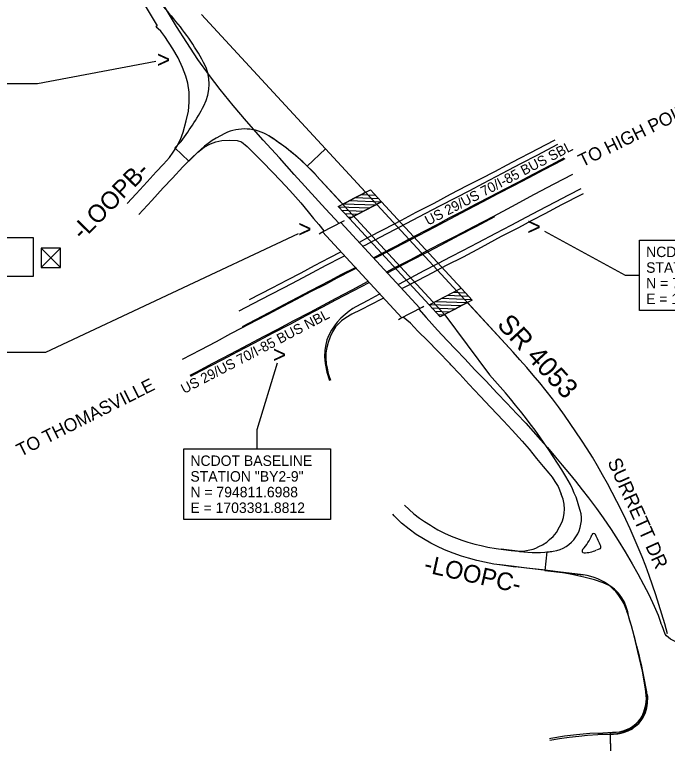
# Model space of a CAD drawing. Extents: x 1701144 to 1707001, y 793349 to 797175.
# Drawn here: x 1702973 to 1703974, y 794216 to 795332 of the extents above; entities that cross this region are included whole.
import ezdxf

# ---------------------------------------------------------------- set-up
doc = ezdxf.new("R2010")
doc.units = 0
for name, color, linetype in [('CTL Sheet Text', 7, 'Continuous'), ('Default', 7, 'Continuous'), ('Exist Property Titlesheet Border PSD CELL', 7, 'Continuous'), ('Old_Level_3', 7, 'Continuous'), ('Old_Level_4', 7, 'Continuous'), ('Old_Level_57', 7, 'Continuous'), ('Prop Approach Slab', 7, 'Continuous'), ('Prop EOT', 7, 'Continuous'), ('Prop Roadway Bridge', 7, 'Continuous'), ('Proposed Right of Way Monument PSD Leader', 7, 'Continuous'), ('Proposed Right of Way Monument PSD Text', 7, 'Continuous'), ('Sheet Title CELL', 7, 'Continuous')]:
    doc.layers.add(name, color=color, linetype=linetype)

msp = doc.modelspace()

# ---------------------------------------------------------------- linework, layer by layer
at = {"layer": 'Default'}
for p, q in [((1703449.8, 795126.4), (1703259.9, 795332.1)), ((1703225.7, 795134.5), (1703218.7, 795127.9)), ((1703218.7, 795127.9), (1703240.5, 795107.5)), ((1703421.5, 795100.2), (1703449.8, 795126.4)), ((1703449.8, 795126.4), (1703421.5, 795100.2)), ((1703511, 795060.1), (1703449.8, 795126.4)), ((1703240.5, 795107.5), (1703248.1, 795115.5)), ((1703435.6, 795085.8), (1703476.2, 795041.8)), ((1703504.1, 795056.5), (1703511, 795060.1)), ((1703476.2, 795041.8), (1703477.5, 795042.5)), ((1703477.5, 795042.5), (1703486.4, 795047.2)), ((1703658.2, 794886.5), (1703649.3, 794881.8)), ((1703667, 794891.1), (1703658.2, 794886.5)), ((1703658.2, 794886.5), (1703658.2, 794886.5)), ((1703658.2, 794886.5), (1703658.2, 794886.5)), ((1703640.4, 794877.2), (1703632.1, 794872.9)), ((1703632.1, 794872.9), (1703632.4, 794872.5)), ((1703632.4, 794872.5), (1703701.1, 794780.4)), ((1703649.3, 794881.8), (1703640.4, 794877.2)), ((1703640.4, 794877.2), (1703640.4, 794877.2)), ((1703640.4, 794877.2), (1703640.4, 794877.2)), ((1703649.3, 794881.8), (1703649.3, 794881.8)), ((1703649.3, 794881.8), (1703649.3, 794881.8)), ((1703788.9, 794509.3), (1703785.5, 794481.1)), ((1703785.5, 794481.1), (1703844.6, 794474)), ((1703890.3, 794230.5), (1703885.6, 794230.3)), ((1703885.6, 794230.3), (1703886.4, 794202.2))]:
    msp.add_line(p, q, dxfattribs=at)
for points in [[(1703486.4, 795047.2), (1703495.2, 795051.8), (1703504.1, 795056.5)], [(1703737.1, 794815.1), (1703667.1, 794891.1), (1703667, 794891.1)]]:
    msp.add_lwpolyline(points, dxfattribs=at)
msp.add_lwpolyline([(1702806, 794990.9), (1703001.6, 794990.9), (1703001.6, 794930.9), (1702806, 794930.9)], close=True, dxfattribs=at)
for centre, radius, start, end in [((1703981.5, 795998.2), 1018, 215.0107, 221.0304), ((1702911.8, 795067.4), 400, 28.6224, 41.0304), ((1703201.5, 795225.4), 70, 332.0106, 28.6224), ((1702910.1, 795380.3), 400, 322.0902, 332.0106), ((1703325.6, 795087), 70, 57.7993, 115.717), ((1703364.7, 795005.9), 160, 115.717, 136.7565), ((1703171.1, 794841.6), 360, 45.9217, 57.7993), ((1703171.1, 794841.6), 360, 42.7091, 45.9217), ((1702989.1, 794124.6), 1018, 14.7589, 42.7091), ((1702989.1, 794124.6), 968, 31.1029, 42.644), ((1703646.7, 794521.4), 200, 14.8969, 31.1029), ((1703791.7, 794559.9), 50, 277.9887, 14.8969), ((1703770.8, 794708.5), 200, 275.1944, 277.9887), ((1703835.1, 794394.6), 80, 17.697, 83.1536), ((1702989.1, 794124.6), 968, 10.146, 17.697), ((1703887.8, 794285.5), 55, 272.5979, 10.146)]:
    msp.add_arc(centre, radius, start, end, dxfattribs=at)
at = {"layer": 'Exist Property Titlesheet Border PSD CELL'}
for points in [[(1703930.9, 794986.8), (1704155.5, 794986.8), (1704155.5, 794878.8), (1703930.9, 794878.8)], [(1703232.7, 794667), (1703457.3, 794667), (1703457.3, 794559), (1703232.7, 794559)]]:
    msp.add_lwpolyline(points, close=True, dxfattribs=at)
at = {"layer": 'Old_Level_3'}
for points in [[(1703167.6, 795356.3), (1703171.7, 795348.1), (1703180.9, 795332.8), (1703191.9, 795315), (1703189.8, 795313.5)], [(1703418.2, 795069.3), (1703401.7, 795087.5), (1703379, 795112.6), (1703354.2, 795139.9), (1703328.7, 795168.8), (1703308, 795193), (1703288.1, 795217.4), (1703271.7, 795238.9), (1703254.2, 795263.5), (1703237.1, 795289.4), (1703221.3, 795314.1), (1703203, 795344.6)], [(1703145.6, 795042.7), (1703159.4, 795057.7), (1703176.4, 795076.1), (1703190.4, 795091.1), (1703201.5, 795103.1), (1703210.6, 795113.4), (1703216.4, 795121.4), (1703222, 795130.2), (1703227.5, 795140.7), (1703231.4, 795152.1), (1703236.1, 795169.3), (1703239.6, 795184.4), (1703240.7, 795197.8), (1703240.8, 795213.5), (1703238.9, 795226.9), (1703235.9, 795237.7), (1703230.6, 795251.2), (1703223.9, 795265.8), (1703215.6, 795279.8), (1703203.6, 795298.5), (1703197.6, 795306.6), (1703193.5, 795310.3), (1703190.1, 795313)], [(1703641.3, 795056.9), (1703666.7, 795070.3), (1703688.3, 795081.2), (1703708.9, 795091.9), (1703727.9, 795102), (1703746.4, 795111.8), (1703764.4, 795120.9), (1703786.8, 795132.8), (1703801.5, 795140.3)], [(1703163.8, 795025.9), (1703183.4, 795047.6), (1703201, 795066.7), (1703215, 795081.9), (1703231.1, 795099.2), (1703243.7, 795111.8), (1703254, 795121.4), (1703264, 795128.9), (1703273.7, 795134.1), (1703281.8, 795137.4), (1703290.8, 795139.5), (1703302.6, 795139.6), (1703314.3, 795139.5), (1703320.8, 795137.4), (1703329.8, 795130.2), (1703351.4, 795108.4), (1703369.9, 795089.4), (1703388.8, 795069.2), (1703399.7, 795057.6)], [(1703804.9, 795133), (1703796.3, 795128.6), (1703774.5, 795117.1), (1703748.6, 795103.5), (1703720.1, 795088.7), (1703691.4, 795073.7), (1703670.1, 795062.4), (1703649.1, 795051.6), (1703624.3, 795038.9)], [(1703816.3, 795111), (1703812.6, 795109.1), (1703784.4, 795094.5), (1703761.4, 795082.3), (1703736.8, 795069.6), (1703713.8, 795057.6), (1703690.6, 795045.5), (1703666.3, 795032.6), (1703639.9, 795018.9)], [(1703657.6, 795030.1), (1703681.7, 795042.7), (1703702.3, 795053.4), (1703723.9, 795064.8), (1703744.8, 795075.7), (1703768.9, 795088.3), (1703795.5, 795102.3), (1703815.3, 795112.6)], [(1703553.8, 794943.6), (1703580.2, 794957.3), (1703601.6, 794968.7), (1703625.3, 794980.9), (1703649.6, 794993.3), (1703676.8, 795007.7), (1703707.5, 795023.6), (1703735.3, 795038.4), (1703770, 795057), (1703800.1, 795072.9), (1703828.4, 795087.7)], [(1703418.2, 795069.3), (1703438.9, 795046.4), (1703449.8, 795034.7), (1703464.1, 795019.5), (1703470.3, 795012.7)], [(1703840.6, 795065.3), (1703821.9, 795055.4), (1703801.4, 795044.9), (1703775.9, 795031.5), (1703757.6, 795021.8), (1703733.6, 795009.3), (1703710.1, 794996.8), (1703682.9, 794982.6)], [(1703399.7, 795057.6), (1703412, 795043.8), (1703423, 795030.3), (1703431.4, 795020), (1703439.3, 795010.5), (1703447.2, 795001)], [(1703501.5, 794983.8), (1703514.6, 794990.7), (1703539.7, 795003.6), (1703566, 795017.5), (1703588.8, 795029.4), (1703616.1, 795043.6), (1703641.3, 795056.9)], [(1703844.4, 795057.9), (1703842.2, 795056.7), (1703811.3, 795040.6), (1703785.7, 795027), (1703765.6, 795016.7), (1703745.2, 795005.7), (1703719, 794992.1), (1703688.3, 794975.5), (1703660.8, 794960.9), (1703634.4, 794948.1)], [(1703624.3, 795038.9), (1703603, 795027.7), (1703582.4, 795016.7), (1703556.3, 795003), (1703532.1, 794990.5), (1703509.9, 794978.7), (1703507.2, 794977.3)], [(1703523.1, 794959.7), (1703533.6, 794965.2), (1703558.3, 794978.2), (1703576.3, 794987.5), (1703601.7, 795000.9), (1703621.7, 795011.2), (1703639.2, 795020.8), (1703657.6, 795030.1)], [(1703639.9, 795018.9), (1703616.1, 795006.3), (1703592.5, 794994.1), (1703568, 794981.2), (1703547.9, 794970.6), (1703526.7, 794959.8), (1703524.1, 794958.5)], [(1703544.8, 794936.7), (1703553.5, 794941.3), (1703580.5, 794955.6), (1703606.6, 794969.1), (1703627, 794979.6), (1703654.7, 794994.2), (1703680.4, 795007.6), (1703709.1, 795022.8)], [(1703682.9, 794982.6), (1703659.8, 794970.5), (1703641.8, 794961.2), (1703621.4, 794950.4), (1703600.4, 794939.5), (1703580.4, 794929), (1703562.3, 794919.2), (1703561.5, 794918.8)], [(1703333.4, 794895.8), (1703367.7, 794913.7), (1703391.2, 794926.1), (1703412.4, 794936.9), (1703432.7, 794947.8), (1703456.1, 794960.1), (1703473.4, 794968.9)], [(1703479.1, 794962.8), (1703474.4, 794960.4)], [(1703474.4, 794960.4), (1703450.3, 794947.8), (1703429, 794936.5), (1703407.2, 794925.2), (1703385.6, 794913.9), (1703364.9, 794903.2), (1703338.5, 794889.1), (1703316.9, 794878)], [(1703497.1, 794943.8), (1703490.2, 794940.1), (1703467.2, 794928.3), (1703449.5, 794919), (1703427.5, 794907.9), (1703404.5, 794895.8), (1703383.5, 794884.8), (1703361.2, 794872.9), (1703343.6, 794863.7), (1703320.8, 794851.9), (1703304.3, 794843.3), (1703281.9, 794831.2), (1703257.8, 794818.4), (1703229.9, 794803.9)], [(1703322.4, 794854.4), (1703342.8, 794865.2), (1703363.4, 794876), (1703386.5, 794888), (1703407.9, 794899.3), (1703426.2, 794909), (1703441.8, 794917.1), (1703457, 794925.2), (1703474.8, 794934.4), (1703495.4, 794945.1)], [(1703543.4, 794938.2), (1703553.8, 794943.6)], [(1703634.4, 794948.1), (1703605, 794932.2), (1703570.1, 794914.4), (1703566.9, 794912.8)], [(1703242.3, 794780), (1703252.3, 794785.2), (1703276.8, 794798.4), (1703304.5, 794812.9), (1703331.5, 794827.1), (1703354.8, 794839.3), (1703376.6, 794850.6), (1703401.3, 794863.6), (1703426.4, 794876.6), (1703445.9, 794887), (1703466.1, 794897.8), (1703490.6, 794910.9), (1703515.2, 794923.7)], [(1703445.6, 794884.8), (1703465.5, 794895.2), (1703493.2, 794909.7), (1703516.8, 794921.9)], [(1703538.8, 794898), (1703535.5, 794896.3), (1703503.7, 794880), (1703489.9, 794873.3), (1703480.8, 794867.9), (1703474.4, 794863.1), (1703469.9, 794859.2), (1703465.2, 794853.8), (1703460.5, 794846.2), (1703456.8, 794838.5), (1703453.5, 794830.1), (1703451.5, 794822.3), (1703450.4, 794814), (1703450.1, 794806.1), (1703450.9, 794797.5), (1703452.1, 794791.3), (1703453.4, 794784.7), (1703454.9, 794779.5), (1703457.4, 794772.5)], [(1703533.3, 794904.4), (1703531.3, 794903.3), (1703514.4, 794894.4), (1703495.9, 794884.6)], [(1703243.3, 794778.4), (1703248, 794780.9), (1703274.6, 794794.9), (1703292.4, 794804.1), (1703315.2, 794816.2), (1703341, 794829.7), (1703368.4, 794844.1), (1703395.3, 794858.1), (1703419.9, 794871.1), (1703445.6, 794884.8)], [(1703495.9, 794884.6), (1703491.4, 794882.2), (1703485.9, 794878), (1703480, 794873.1), (1703473.4, 794867.1), (1703467.5, 794861.3), (1703463.2, 794855.6), (1703458.8, 794849.1), (1703454.6, 794841.2), (1703451.9, 794834.1), (1703450, 794826.7), (1703448.6, 794818.4), (1703448.3, 794807.9), (1703449, 794797.8), (1703451.8, 794784.6), (1703455.6, 794771.9)], [(1703592.7, 794881), (1703604, 794868.1), (1703621.2, 794849.1), (1703636.1, 794833.2), (1703649.1, 794819.4), (1703663.1, 794804.9), (1703678.7, 794788.1), (1703695.1, 794771.1), (1703712.9, 794752.3), (1703727.4, 794737), (1703742.7, 794720.6), (1703756.4, 794706.3), (1703767.6, 794693.8), (1703779.2, 794680.9), (1703789.6, 794669.2), (1703802, 794654.4), (1703812.3, 794642.3), (1703823.3, 794628.9), (1703832.6, 794617.6), (1703842.9, 794604.6), (1703852.7, 794591.9), (1703864.9, 794575.6), (1703875.1, 794561.5), (1703887.2, 794543.8), (1703898.1, 794526.8), (1703908.6, 794509.4), (1703919.6, 794491), (1703928.4, 794475.7), (1703937, 794459.5), (1703945, 794443.9), (1703953.2, 794426.2), (1703959.1, 794412.4), (1703963.5, 794400.4)], [(1703641.7, 794796), (1703640.5, 794797.3), (1703621.6, 794816.8), (1703606.4, 794832.6), (1703591.3, 794847.6), (1703579.8, 794859.4), (1703568.9, 794869)], [(1703641.7, 794796), (1703655.4, 794781.3), (1703669.5, 794766.4), (1703686.6, 794748), (1703702.3, 794731.2), (1703722.2, 794710.1), (1703735.4, 794695.8), (1703750.8, 794678.8), (1703761.5, 794666.8), (1703773.1, 794652.4), (1703783.3, 794640.2), (1703791.8, 794630), (1703796.8, 794623.6), (1703801.1, 794617.2), (1703805.9, 794609.5), (1703810.9, 794598)], [(1703570.9, 794580.8), (1703577.8, 794574.1), (1703584.9, 794567.9), (1703593.7, 794561), (1703601.2, 794555.9), (1703610.3, 794550.1), (1703614.9, 794547.2), (1703622, 794543.2), (1703632, 794538.1), (1703642.1, 794533.6), (1703650.3, 794530.4), (1703658.4, 794527.5), (1703667.9, 794524.3), (1703678.3, 794521.3), (1703688, 794519), (1703698.5, 794516.8), (1703710.9, 794514.4), (1703722.4, 794512.8), (1703734, 794511.3), (1703745.5, 794510.6), (1703752.4, 794510.7), (1703757.6, 794511.4), (1703762.5, 794512.3), (1703767.6, 794513.7), (1703771.9, 794515.2), (1703776.4, 794517.4), (1703782.2, 794520.3), (1703788.6, 794524.5), (1703793, 794528.2), (1703798.5, 794532.9), (1703803.4, 794538.9), (1703808.3, 794547.8), (1703812, 794555.6), (1703814.1, 794562), (1703815.5, 794568.8), (1703815.9, 794574.9), (1703815.4, 794582.3), (1703813.8, 794590.2), (1703810.9, 794598)], [(1703923.2, 794378.6), (1703918.6, 794396.1), (1703914.6, 794409.3), (1703912.8, 794417.7), (1703910.5, 794425.4), (1703907.5, 794432.5), (1703903.6, 794439), (1703898.5, 794446), (1703892.5, 794452.3), (1703885.3, 794457.6), (1703875.3, 794462.1), (1703861.6, 794466.7), (1703845.3, 794470.9), (1703827, 794474.7), (1703805.5, 794478.6), (1703782.1, 794482), (1703757.7, 794484.7), (1703738.8, 794486.8), (1703721.9, 794488.8), (1703707.8, 794490.6), (1703693.4, 794493.5), (1703681.6, 794496), (1703668.5, 794499.6), (1703657.9, 794502.8), (1703645.3, 794507.3), (1703632.2, 794512.7), (1703620.2, 794518.1), (1703611.1, 794522.7), (1703599.7, 794529.4), (1703588.7, 794536.2), (1703577.7, 794544.2), (1703566.3, 794553.6), (1703554.9, 794564.4), (1703552.6, 794566.9)], [(1704043.7, 794444.9), (1704039.7, 794420.4), (1704035.4, 794403), (1704031.7, 794391.8), (1704027.1, 794381.3), (1704020.5, 794372.2), (1704013.2, 794367.6), (1704006.7, 794365), (1703997.6, 794366.2), (1703986.4, 794371.5), (1703978, 794375.9), (1703971.9, 794380.8), (1703969.9, 794383.6), (1703965.5, 794396), (1703963.5, 794400.4)], [(1703940.7, 794289.9), (1703939.8, 794299.5), (1703935.3, 794326.7), (1703928.4, 794357), (1703923.2, 794378.6)], [(1703792.7, 794223.6), (1703795.1, 794224), (1703815.9, 794227.6), (1703834.4, 794229.8), (1703854.5, 794231.9), (1703874.6, 794232.5), (1703889.3, 794233.1), (1703895.2, 794233.2), (1703900.2, 794234), (1703905.6, 794235.2), (1703910.8, 794237.2), (1703915.7, 794239.5), (1703920.6, 794242.7), (1703924.9, 794246), (1703929, 794250.1), (1703932.1, 794253.9), (1703934.6, 794258), (1703937.5, 794264.4), (1703940.5, 794275.2), (1703941.2, 794284.2), (1703940.7, 794289.9)], [(1703793.1, 794220.9), (1703793.1, 794220.9), (1703808.4, 794223.4), (1703823, 794225.6), (1703837.6, 794227.3), (1703851.1, 794228.6), (1703866.9, 794229.6), (1703881.7, 794230.1), (1703890.8, 794230.4), (1703897.3, 794230.9), (1703902.6, 794231.9), (1703907.7, 794233.3), (1703913.6, 794235.4), (1703919.8, 794238.6), (1703924.7, 794242.3), (1703929.7, 794246.6), (1703933.4, 794251), (1703936.4, 794255.9), (1703939.9, 794263.3), (1703942, 794270.7), (1703943.1, 794277.9), (1703943.3, 794287.3), (1703942.9, 794290.8)]]:
    msp.add_lwpolyline(points, dxfattribs=at)
at = {"layer": 'Old_Level_4'}
for points in [[(1703439.9, 794996.6), (1703444.2, 794999), (1703476.5, 795015.7), (1703478.7, 795016.8)], [(1703594.4, 794882.7), (1703473.3, 795013.7)], [(1703445.1, 794999.6), (1703566.6, 794867.9)], [(1703561.4, 794865.4), (1703564.2, 794866.6), (1703597.7, 794884.2), (1703600.4, 794885.5)]]:
    msp.add_lwpolyline(points, dxfattribs=at)
at = {"layer": 'Old_Level_57'}
for p, q in [((1703013.9, 794974.6), (1703043.4, 794945.1)), ((1703043.4, 794974.6), (1703013.9, 794945.1))]:
    msp.add_line(p, q, dxfattribs=at)
msp.add_lwpolyline([(1703013.9, 794945.1), (1703043.4, 794945.1), (1703043.4, 794974.6), (1703013.9, 794974.6)], close=True, dxfattribs=at)
for points in [[(1703028.6, 794959.9), (1703043.4, 794974.6), (1703013.9, 794974.6), (1703028.6, 794959.9)], [(1703028.6, 794959.9), (1703013.9, 794945.1), (1703043.4, 794945.1), (1703028.6, 794959.9)]]:
    msp.add_lwpolyline(points, dxfattribs=at)
at = {"layer": 'Prop Approach Slab'}
for p, q in [((1703469.3, 795038.2), (1703518.4, 795064)), ((1703518.4, 795064), (1703535.3, 795045.6)), ((1703495.2, 795051.8), (1703530.8, 795050.4)), ((1703504.1, 795056.5), (1703526, 795055.6)), ((1703477.5, 795042.5), (1703525.8, 795040.6)), ((1703486.2, 795019.9), (1703530.3, 795042.9)), ((1703486.4, 795047.2), (1703534.7, 795045.3)), ((1703486.2, 795019.9), (1703469.3, 795038.2)), ((1703469.6, 795037.9), (1703517, 795036)), ((1703474.4, 795032.7), (1703508.1, 795031.3)), ((1703479.2, 795027.5), (1703499.2, 795026.7)), ((1703484, 795022.3), (1703490.3, 795022)), ((1703653.2, 794917.8), (1703674.4, 794894.9)), ((1703645.4, 794907), (1703663.9, 794906.2)), ((1703627.6, 794897.7), (1703673.5, 794895.9)), ((1703636.5, 794902.3), (1703668.7, 794901)), ((1703608.3, 794887.6), (1703625.3, 794869.3)), ((1703609.8, 794888.4), (1703658.2, 794886.5)), ((1703612.3, 794883.3), (1703649.3, 794881.8)), ((1703618.7, 794893), (1703667.1, 794891.1)), ((1703617.1, 794878.1), (1703640.4, 794877.2)), ((1703621.9, 794872.9), (1703631.5, 794872.5))]:
    msp.add_line(p, q, dxfattribs=at)
for points in [[(1703518.4, 795064), (1703535.3, 795045.6), (1703486.2, 795019.9), (1703469.3, 795038.2)], [(1703657.4, 794913.3), (1703674.4, 794894.9), (1703625.3, 794869.3), (1703608.3, 794887.6)]]:
    msp.add_lwpolyline(points, close=True, dxfattribs=at)
at = {"layer": 'Prop EOT'}
for p, q in [((1703259.9, 795332.1), (1703737.1, 794815.1)), ((1703218.7, 795127.9), (1703225.7, 795134.5)), ((1703218.7, 795127.9), (1703240.5, 795107.5)), ((1703240.5, 795107.5), (1703248.1, 795115.5)), ((1703435.6, 795085.8), (1703632.4, 794872.5)), ((1703632.4, 794872.5), (1703701.1, 794780.4)), ((1703743.8, 794510.3), (1703719, 794513.3)), ((1703749.4, 794509.6), (1703743.8, 794510.3)), ((1703788.9, 794509.3), (1703785.5, 794481.1)), ((1703869.8, 794514.1), (1703864.6, 794511.9)), ((1703716, 794490), (1703740.8, 794486.5)), ((1703844.6, 794474), (1703740.8, 794486.5)), ((1703890.3, 794230.5), (1703866.7, 794229.5)), ((1703885.6, 794232.7), (1703886.5, 794197.2))]:
    msp.add_line(p, q, dxfattribs=at)
for centre, radius, start, end in [((1703981.5, 795998.2), 1018, 215.0107, 221.0304), ((1702911.8, 795067.4), 400, 28.6224, 41.0304), ((1703201.5, 795225.4), 70, 332.0106, 28.6224), ((1702910.1, 795380.3), 400, 322.0902, 332.0106), ((1703325.6, 795087), 70, 57.7993, 115.717), ((1703364.7, 795005.9), 160, 115.717, 136.7565), ((1703171.1, 794841.6), 360, 42.7091, 57.7993), ((1702989.1, 794124.6), 1018, 14.7589, 42.7091), ((1702989.1, 794124.6), 968, 31.1029, 42.644), ((1703646.7, 794521.4), 200, 14.8969, 31.1029), ((1703791.7, 794559.9), 50, 277.9887, 14.8969), ((1703860.5, 794534.6), 3, 25.1924, 159.3051), ((1703794.1, 794559.6), 68, 316.63, 339.3051), ((1702989.1, 794124.6), 966, 24.0356, 25.1924), ((1703868.6, 794516.9), 3, 292.6149, 24.0356), ((1703770.8, 794708.5), 200, 263.1536, 277.9887), ((1703845.7, 794510.9), 3, 136.63, 271.7512), ((1703844.2, 794560.9), 53, 271.7512, 292.6149), ((1703835.1, 794394.6), 80, 17.697, 83.1536), ((1702989.1, 794124.6), 968, 10.146, 17.697), ((1703887.8, 794285.5), 55, 272.5979, 10.146)]:
    msp.add_arc(centre, radius, start, end, dxfattribs=at)
at = {"layer": 'Prop Roadway Bridge'}
for p, q in [((1703486.2, 795019.9), (1703535.3, 795045.6)), ((1703535.3, 795045.6), (1703657.4, 794913.3)), ((1703486.2, 795019.9), (1703608.3, 794887.6)), ((1703608.3, 794887.6), (1703657.4, 794913.3))]:
    msp.add_line(p, q, dxfattribs=at)
at = {"layer": 'Proposed Right of Way Monument PSD Leader'}
for points in [[(1702957.1, 795226.8), (1703008.6, 795226.8), (1703189.9, 795260.7)], [(1702934.1, 794815.1), (1703021.2, 794815.1), (1703408.2, 794996.8)], [(1703930.9, 794932.8), (1703909.2, 794932.8), (1703785.7, 794999.9)], [(1703345, 794667), (1703345, 794696.6), (1703376.2, 794798.7)]]:
    msp.add_lwpolyline(points, dxfattribs=at)

# ---------------------------------------------------------------- texts
at = {"layer": 'CTL Sheet Text'}
for s, rotation, p in [('TO HIGH POINT', 26.1672, (1703843.1, 795098.2)), ('TO THOMASVILLE', 26.5637, (1702982.5, 794654.7))]:
    msp.add_text(s, height=20, rotation=rotation, dxfattribs=at).set_placement(p)
at = {"layer": 'Old_Level_57'}
for p in [(1703191.2, 795250.5), (1703407.8, 794991.1), (1703758.9, 794994.7), (1703368.8, 794798.7)]:
    msp.add_text('>', height=26.1, rotation=0.0142, dxfattribs=at).set_placement(p)
at = {"layer": 'Proposed Right of Way Monument PSD Text'}
for s, p in [('NCDOT BASELINE', (1703940.9, 794960.8)), ('STATION "BY2-8"', (1703940.9, 794936.8)), ('N = 795007.7300', (1703940.9, 794912.8)), ('E = 1703771.9500', (1703940.9, 794888.8)), ('NCDOT BASELINE', (1703242.7, 794641)), ('STATION "BY2-9"', (1703242.7, 794617)), ('N = 794811.6988', (1703242.7, 794593)), ('E = 1703381.8812', (1703242.7, 794569))]:
    msp.add_text(s, height=16, dxfattribs=at).set_placement(p)
at = {"layer": 'Sheet Title CELL'}
for s, height, rotation, p in [('US 29/US 70/I-85 BUS SBL', 15.259, 27.5803, (1703606.9, 795008.7)), ('-LOOPB-', 27, 45.445, (1703077.3, 794985.6)), ('US 29/US 70/I-85 BUS NBL', 15.259, 27.5467, (1703233.1, 794751.1)), ('SR 4053', 30, 312.7091, (1703711.1, 794856.4)), ('SURRETT DR', 21.16, 294.2459, (1703881.2, 794647.4)), ('-LOOPC-', 27, 347.3903, (1703599.1, 794478.8))]:
    msp.add_text(s, height=height, rotation=rotation, dxfattribs=at).set_placement(p)

doc.saveas('drawing.dxf')
